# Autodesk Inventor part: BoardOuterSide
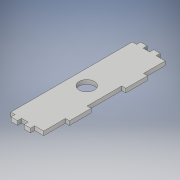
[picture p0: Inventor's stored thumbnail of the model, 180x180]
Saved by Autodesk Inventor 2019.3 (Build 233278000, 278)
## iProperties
Created: 2020-03
Part Number: BoardOuterSide
Material: Generic
Document SubType Name: Modeling
Designer: KrystynWikoff
Density: 1 g/cm^3
Appearance: Default
Author: KrystynWikoff
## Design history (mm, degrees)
sketch "Sketch1"
  geometry: L1 (0, 0)-(21.59, 0); L2 (21.59, 0)-(21.59, -75.824); L3 (21.59, -75.824)-(0, -75.824); L4 (0, -75.824)-(0, 0)
  constraints: 8 end point, 2 parallel, 1 horizontal, 1 perpendicular
  dimensions: "d0" = 21.59 distance of L2.end L3.end; "d1" = 75.8244 distance of L1.end L2.end
extrude "Extrusion1" new body sketch "Sketch1" distance "d2" = 2.3622; taper "d3" = 0 deg
sketch "Sketch4" dims "d44" = 25.4
  geometry: L1 (-3.81, 0)-(-7.62, 0); L2 (-7.62, 0)-(-7.62, 2.362); L3 (-7.62, 2.362)-(-3.81, 2.362); L4 (-3.81, 2.362)-(-3.81, 0); L5 (0, 0)-(0, 75.824) reference; L6 (-21.59, 0)-(0, 0) reference; L7 (-11.43, 0)-(-15.24, 0); L8 (-15.24, 0)-(-15.24, 2.362); L9 (-15.24, 2.362)-(-11.43, 2.362); L10 (-11.43, 2.362)-(-11.43, 0); L11 (-3.81, 0)-(0, 0); L12 (0, 0)-(0, 2.362); L13 (0, 2.362)-(-3.81, 2.362); L14 (-3.81, 2.362)-(-3.81, 0); L15 (0, 75.824)-(-3.81, 75.824); L16 (-3.81, 75.824)-(-3.81, 73.462); L17 (-3.81, 73.462)-(0, 73.462); L18 (0, 73.462)-(0, 75.824); L19 (0, 75.824)-(-21.59, 75.824) reference; L20 (-3.81, 73.462)-(-7.62, 73.462); L21 (-7.62, 73.462)-(-7.62, 75.824); L22 (-7.62, 75.824)-(-3.81, 75.824); L23 (-3.81, 75.824)-(-3.81, 73.462); L24 (-11.43, 75.824)-(-15.24, 75.824); L25 (-15.24, 75.824)-(-15.24, 73.462); L26 (-15.24, 73.462)-(-11.43, 73.462); L27 (-11.43, 73.462)-(-11.43, 75.824)
  constraints: 48 end point, 10 parallel, 6 horizontal, 5 perpendicular, 3 point on line, 1 collinear, 7 other
  dimensions: "d35" = 3.81 distance of L2.end L3.end; "d36" = 3.81 distance between parallel lines of L5 L4; "d37" = 2.3622 distance of L1.end L2.end; "d38" = 0 distance between parallel lines of L6 L1; "d41" = 7.62 distance of L1.start L7.start; "d46" = 2.3622 distance of L11.end L12.end; "d47" = 3.81 distance of L16.end L17.end; "d48" = 2.3622 distance of L15.end L16.end; "d49" = 3.81 distance of L16.end L20.end; "d50" = 3.81 distance of L25.end L26.end; "d51" = 2.3622 distance of L26.end L24.start; "d52" = 3.81 distance between parallel lines of L21 L27
extrude "Extrusion4" cut sketch "Sketch4" distance "d53" = 25.4; taper "d54" = 0 deg
sketch "Sketch6"
  geometry: L1 (-7.62, 2.362)-(0, 2.362) reference; L2 (0, 2.362)-(-2.362, 2.362); L3 (-2.362, 2.362)-(-2.362, 15.062); L4 (-2.362, 15.062)-(0, 15.062); L5 (0, 15.062)-(0, 2.362); L6 (0, 2.362)-(0, 73.462) reference; L7 (0, 73.462)-(-2.362, 73.462); L8 (-2.362, 73.462)-(-2.362, 60.762); L9 (-2.362, 60.762)-(0, 60.762); L10 (0, 60.762)-(0, 73.462); L11 (0, 27.762)-(-2.362, 27.762); L12 (-2.362, 27.762)-(-2.362, 48.062); L13 (-2.362, 48.062)-(0, 48.062); L14 (0, 48.062)-(0, 27.762); 1 further point
  constraints: 24 end point, 6 parallel, 3 horizontal, 3 perpendicular, 1 point on line
  dimensions: "d66" = 12.7 distance of L2.end L3.end; "d67" = 2.3622 distance of L3.end L4.end; "d68" = 12.7 distance of L7.end L8.end; "d69" = 2.3622 distance of L8.end L9.end; "d70" = 12.7 distance between parallel lines of L4 L11; "d71" = 12.7 distance between parallel lines of L9 L13; "d72" = 2.3622 distance of L11.start L11.end
extrude "Extrusion6" cut sketch "Sketch6" distance "d73" = 25.4; taper "d74" = 0 deg
sketch "Sketch7"
  geometry: L1 (-21.59, 75.824)-(-21.59, 0) reference; L2 (-19.05, 0)-(-21.59, 0); L3 (-21.59, 0)-(-21.59, 2.362); L4 (-21.59, 2.362)-(-19.05, 2.362); L5 (-19.05, 2.362)-(-19.05, 0); L6 (-15.24, 0)-(-15.24, 2.362) reference; L7 (-21.59, 0)-(-15.24, 0) reference; L8 (-21.59, 75.824)-(-19.05, 75.824); L9 (-19.05, 75.824)-(-19.05, 73.462); L10 (-19.05, 73.462)-(-21.59, 73.462); L11 (-21.59, 73.462)-(-21.59, 75.824); L12 (-15.24, 73.462)-(-15.24, 75.824) reference; 1 further point
  constraints: 16 end point, 4 parallel, 2 horizontal, 2 perpendicular, 1 point on line
  dimensions: "d75" = 3.81 distance between parallel lines of L6 L5; "d76" = 2.3622 distance of L4.end L2.start; "d77" = 2.3622 distance between parallel lines of L7 L4; "d78" = 2.3622 distance of L8.end L9.end; "d79" = 3.81 distance between parallel lines of L12 L9
extrude "Extrusion7" cut sketch "Sketch7" distance "d80" = 25.4; taper "d81" = 0 deg
sketch "Sketch8"
  geometry: L1 (0, 48.062)-(0, 60.762) reference; L2 (-19.05, 0)-(-15.24, 0) reference; C1 r 4.445 at (-12.7, 37.909); 1 further point
  constraints: 1 centre point
  dimensions: "d82" = 8.89 diameter of C1; "d83" = 12.7 distance from line of L1 C1.centre; "d84" = 37.9095 distance from line of L2 C1.centre
extrude "Extrusion8" cut sketch "Sketch8" distance "d85" = 25.4; taper "d86" = 0 deg
body "Solid1"
